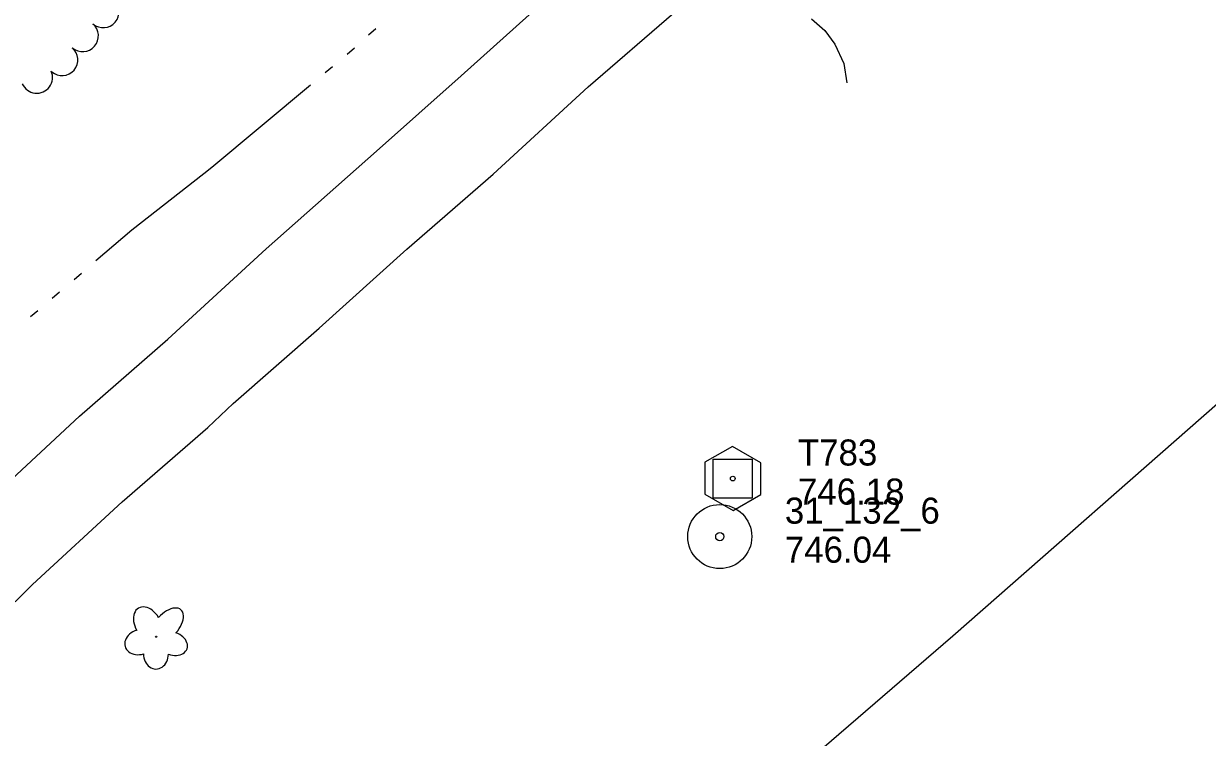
# Model space of a CAD drawing. Extents: x 589250 to 1188077, y 162953 to 363065.
# Drawn here: x 594538 to 594810.7, y 173832.9 to 173997.3 of the extents above; entities that cross this region are included whole.
import ezdxf

# ---------------------------------------------------------------- set-up
doc = ezdxf.new("R2010")
doc.units = 0
for name, color, linetype in [('E_DWY', 7, 'Continuous'), ('E_LAND_TreeLine_P', 7, 'Continuous'), ('E_LAND_Vegetation', 7, 'Continuous'), ('E_MAP_Control', 7, 'Continuous'), ('E_MAP_Limits', 7, 'Continuous'), ('E_MAP_PassPoints', 7, 'Continuous'), ('E_RDWY', 7, 'Continuous'), ('E_WTR_FlowLine', 7, 'Continuous')]:
    doc.layers.add(name, color=color, linetype=linetype)

msp = doc.modelspace()

# ---------------------------------------------------------------- linework, layer by layer
at = {"layer": 'E_DWY'}
for p, q in [((594719.44, 173998.43), (594722.57, 173995.77)), ((594722.57, 173995.77), (594724.87, 173992.61)), ((594724.87, 173992.61), (594726.93, 173988.11)), ((594726.93, 173988.11), (594727.65, 173983.67))]:
    msp.add_line(p, q, dxfattribs=at)
at = {"layer": 'E_LAND_TreeLine_P'}
for centre, start, end in [((594556.28, 174000.03), 229.303, 49.303), ((594551.53, 173994.51), 229.303, 49.303), ((594546.79, 173989), 229.303, 49.303), ((594540.97, 173984.93), 203.3939, 23.3939)]:
    msp.add_arc(centre, 3.64, start, end, dxfattribs=at)
at = {"layer": 'E_LAND_Vegetation'}
msp.add_circle((594568.48, 173856.07), 0.128, dxfattribs=at)
for centre, major_axis, ratio in [((594566.52, 173859), (2.11, -3.66), 0.691916), ((594571.04, 173858.72), (-3.15, -3.56), 0.560249), ((594564.78, 173854.83), (3.47, 1.01), 0.782863), ((594572.18, 173854.51), (-3.42, 1.21), 0.716896), ((594568.44, 173852.08), (0.03, 3.45), 0.832022)]:
    msp.add_ellipse(centre, major_axis=major_axis, ratio=ratio, start_param=1.570796, end_param=4.712389, dxfattribs=at)
at = {"layer": 'E_MAP_Control'}
for p, q in [((594696.84, 173888.01), (594696.84, 173897.01)), ((594696.84, 173897.01), (594705.84, 173897.01)), ((594696.84, 173888.01), (594696.84, 173897.01)), ((594696.84, 173897.01), (594705.84, 173897.01)), ((594696.84, 173888.01), (594696.84, 173897.01)), ((594696.84, 173897.01), (594705.84, 173897.01)), ((594705.84, 173897.01), (594705.84, 173888.01)), ((594705.84, 173897.01), (594705.84, 173888.01)), ((594705.84, 173897.01), (594705.84, 173888.01)), ((594705.84, 173888.01), (594696.84, 173888.01)), ((594705.84, 173888.01), (594696.84, 173888.01)), ((594705.84, 173888.01), (594696.84, 173888.01))]:
    msp.add_line(p, q, dxfattribs=at)
msp.add_lwpolyline([(594694.93, 173896.27), (594694.93, 173888.88), (594701.39, 173885.16), (594707.79, 173888.82), (594707.79, 173896.15), (594701.26, 173899.87)], close=True, dxfattribs=at)
msp.add_lwpolyline([(594694.93, 173896.27), (594694.93, 173888.88), (594701.39, 173885.16), (594707.79, 173888.82), (594707.79, 173896.15), (594701.26, 173899.87)], close=True, dxfattribs=at)
msp.add_lwpolyline([(594694.93, 173896.27), (594694.93, 173888.88), (594701.39, 173885.16), (594707.79, 173888.82), (594707.79, 173896.15), (594701.26, 173899.87)], close=True, dxfattribs=at)
msp.add_circle((594701.34, 173892.51), 0.546, dxfattribs=at)
msp.add_circle((594701.34, 173892.51), 0.546, dxfattribs=at)
msp.add_circle((594701.34, 173892.51), 0.546, dxfattribs=at)
at = {"layer": 'E_MAP_Limits'}
for p, q in [((594826.27, 173921.41), (594752.03, 173856.23)), ((594752.03, 173856.23), (594706.78, 173817.16))]:
    msp.add_line(p, q, dxfattribs=at)
at = {"layer": 'E_MAP_PassPoints'}
for radius in [7.38, 7.38, 7.38, 0.945, 0.945, 0.945]:
    msp.add_circle((594698.34, 173879.14), radius, dxfattribs=at)
at = {"layer": 'E_RDWY'}
for p, q in [((594638.78, 173985.33), (594664.48, 174008.44)), ((594668.05, 173982.73), (594687.78, 173999.83)), ((594619.22, 173967.91), (594638.78, 173985.33)), ((594646.09, 173962.65), (594668.05, 173982.73)), ((594593.84, 173945.46), (594619.22, 173967.91)), ((594626.2, 173945.39), (594646.09, 173962.65)), ((594571.14, 173924.66), (594593.84, 173945.46)), ((594606, 173927.13), (594626.2, 173945.39)), ((594586.22, 173909.84), (594606, 173927.13)), ((594550.79, 173906.85), (594571.14, 173924.66)), ((594580.36, 173904.31), (594586.22, 173909.84)), ((594528.89, 173886.53), (594550.79, 173906.85)), ((594560.67, 173887.17), (594580.36, 173904.31)), ((594539.97, 173868.09), (594560.67, 173887.17)), ((594524.97, 173853.3), (594539.97, 173868.09))]:
    msp.add_line(p, q, dxfattribs=at)
at = {"layer": 'E_WTR_FlowLine'}
for p, q in [((594619.07, 173996.1), (594617.43, 173994.63)), ((594614.14, 173991.69), (594612.5, 173990.22)), ((594609.13, 173987.38), (594607.43, 173985.97)), ((594604.05, 173983.14), (594581.34, 173964.21)), ((594581.34, 173964.21), (594579.45, 173962.73)), ((594579.45, 173962.73), (594562.87, 173949.76)), ((594562.87, 173949.76), (594554.58, 173942.64)), ((594551.24, 173939.77), (594549.57, 173938.33)), ((594546.22, 173935.46), (594544.55, 173934.02)), ((594541.2, 173931.15), (594539.5, 173929.75)), ((594541.2, 173931.15), (594541.2, 173931.15))]:
    msp.add_line(p, q, dxfattribs=at)

# ---------------------------------------------------------------- texts
at = {"layer": 'E_MAP_Control'}
for s, p in [('T783', (594716.35, 173895.51)), ('T783', (594716.35, 173895.51)), ('T783', (594716.35, 173895.51)), ('746.18', (594716.35, 173886.51)), ('746.18', (594716.35, 173886.51)), ('746.18', (594716.35, 173886.51))]:
    msp.add_text(s, height=6, dxfattribs=at).set_placement(p)
at = {"layer": 'E_MAP_PassPoints'}
for s, p in [('31_132_6', (594713.34, 173882.12)), ('31_132_6', (594713.34, 173882.12)), ('31_132_6', (594713.34, 173882.12)), ('746.04', (594713.34, 173873.12)), ('746.04', (594713.34, 173873.12)), ('746.04', (594713.34, 173873.12))]:
    msp.add_text(s, height=6, dxfattribs=at).set_placement(p)

doc.saveas('drawing.dxf')
